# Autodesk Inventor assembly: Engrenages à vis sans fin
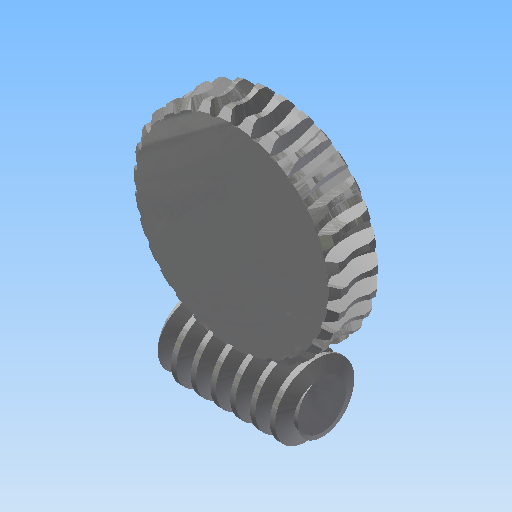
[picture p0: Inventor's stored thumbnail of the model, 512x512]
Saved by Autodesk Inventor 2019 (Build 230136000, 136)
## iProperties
ClientObjectVersion: 1
Created: 2023-04
Part Number: Engrenages à vis sans fin
Document SubType Name: Assembly
Designer: Thier
Categories: <?xml version="1.0" encoding="UTF-16"?> <MemberInstance><Categories><FamilyTemplate/><ParamToTemplateMap><ParamToTemplate><ParamToTemplate CategoryParameter="//
Author: Thier
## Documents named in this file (3)
- C:\Travail\PREPA\EC02\TP\TP3-Arbre\EC02-T03-Pieces-SEMoteur\SERoueVis\Design Accelerator\Engrenages à vis sans fin1.iam
- C:\Travail\PREPA\EC02\TP\TP3-Arbre\EC02-T03-Pieces-SEMoteur\SERoueVis\Design Accelerator\Vis sans fin1.ipt
- C:\Travail\PREPA\EC02\TP\TP3-Arbre\EC02-T03-Pieces-SEMoteur\SERoueVis\Design Accelerator\Engrenage à vis sans fin1.ipt
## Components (2 placed, 2 different names)
1. Vis sans fin:1 — Rotation:1
2. Engrenage à vis sans fin:1 — Rotation:1
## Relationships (1: RelateRotation 1)
- Rotation:1 [RelateRotation]: Vis sans fin:1 ↔ Engrenage à vis sans fin:1
